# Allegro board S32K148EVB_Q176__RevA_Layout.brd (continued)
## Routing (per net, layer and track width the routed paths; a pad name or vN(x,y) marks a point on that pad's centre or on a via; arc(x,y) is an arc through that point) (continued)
PTE10/CLKOUT/LPSPI2_PCS1/FTM2_C: length 203.9
  TOP w0.16: U7.6 v1(74.79,63.24) ; U8.11 v1(74.3,68.04)
  TOP w0.406: R219.1 v1(100.42,41.74) ; v1(33.72,12.15) 33.62,12.05 33.39,12.05 R310.1
  L3_INT_1 w0.191: v1(33.72,12.15) 33.72,14.58 24.89,23.42 24.89,42.47 25.25,42.84 25.25,45.71 24.95,46.01 24.95,47.7 26.09,48.84 26.09,55.95 25.25,56.78 25.25,59.29 26.22,60.25 26.22,60.9 26.24,60.93 26.24,60.96 26.25,60.96 26.25,61.36 26.22,61.38 26.22,68.27 18.6,75.89 18.29,75.89 17.34,76.84 17.34,82.65 18.3,83.61 21.75,83.61 22.73,82.63 22.73,79.53 23.38,78.87 25.28,78.87 J2.20 ; v1(84.54,59.04) 91.76,51.82 91.76,42.86 93.35,41.27 99.94,41.27 v1(100.42,41.74)
  L6_INT_2 w0.191: v1(84.54,59.04) 85.31,59.81 85.31,62.67 83.93,64.04 ; J2.20 27.81,78.54 27.81,76.99 30.23,74.56 38.67,74.56 38.78,74.45 43.83,74.45 51.01,67.26 52.24,67.26 52.74,66.76
  L6_INT_2 w0.203: 52.74,66.76 55.79,66.76 56.17,66.38 73.28,66.38 74.3,67.39 v1(74.3,68.04) ; 83.93,64.04 83.38,64.6 82.44,64.6 81.55,65.49 78.98,65.49 77.33,63.84 75.5,63.84 74.9,63.24 v1(74.79,63.24)
  BOTTOM w0.16: v1(74.3,68.04) 74.3,66.75 74.79,66.26 v1(74.79,63.24)
PTE11/FTM2_CH5/FXIO_D5: length 158.4
  TOP w0.16: U7.5 v1(75.29,62.77) ; U8.10 v1(74.8,67.57)
  TOP w0.406: R309.1 31.43,11.87 31.43,12.21 31.48,12.25 v1(31.48,12.22)
  L3_INT_1 w0.191: v1(31.48,12.22) 31.48,16.37 24.57,23.29 24.57,42.6 24.93,42.97 24.93,45.58 24.63,45.88 24.63,47.84 25.77,48.98 25.77,55.79 24.94,56.63 24.94,61.21 25.74,62.01 25.74,62.02 25.76,62.04 25.76,62.44 25.74,62.46 25.74,68.31 18.47,75.58 18.16,75.58 17.02,76.71 17.02,82.78 18.17,83.93 23.98,83.93 24.94,82.96 24.94,81.07 J2.23
  L6_INT_2 w0.191: J2.23 24.95,78.86 24.95,77.3 28.02,74.24 38.55,74.24 38.65,74.13 43.69,74.13 50.88,66.95 51.98,66.95 52.52,66.41 52.74,66.41
  L6_INT_2 w0.203: 52.74,66.41 55.64,66.41 56.03,66.03 73.73,66.03 74.8,67.09 v1(74.8,67.57)
  BOTTOM w0.16: v1(75.29,62.77) 75.29,67.08 v1(74.8,67.57)
PTE12/FTM0_FLT3/LPUART2_TX/FTM5: length 37.4
  TOP w0.16: U8.30 v1(64.79,67.57) ; U7.23 v1(66.29,62.77)
  L3_INT_1 w0.191: J6.20 74.73,78.54 74.73,76.97 74.08,76.32 73.16,76.32 72.19,77.29 72.19,80.43 71.54,81.08 68.08,81.08 65.7,78.7 65.7,73.21 64.79,72.3 64.79,69.05
  L3_INT_1 w0.203: 64.79,69.05 v1(64.79,67.57)
  BOTTOM w0.16: v1(64.79,67.57) 64.79,66.23 66.29,64.72 v1(66.29,62.77)
PTE13/FTM4_CH5/LPSPI2_PCS2/FTM2: length 95.7
  TOP w0.16: U7.7 v1(74.29,62.77) ; U8.12 v1(73.8,67.57)
  TOP w0.406: J6.23 74.84,78.75 74.84,76.86 v1(75.95,75.75) ; R220.1 v1(101.43,41.74)
  L3_INT_1 w0.191: J6.23 74.97,81.32 74.97,82.87 75.95,83.86 91.61,83.86 94.04,81.42 94.04,76.54 98.76,71.82 98.76,60.66 96.72,58.61 96.72,56.56 96.24,56.08 96.24,55.47 93.52,52.75 93.52,47.65 94.32,46.84 94.55,46.84 98.83,42.56 101.1,42.56 101.43,42.22 v1(101.43,41.74)
  BOTTOM w0.16: v1(74.29,62.77) 74.29,66.28 73.8,66.78 v1(73.8,67.57)
  BOTTOM w0.203: 73.8,69.05 v1(73.8,67.57)
  BOTTOM w0.406: v1(75.95,75.75) 76.36,75.34 76.36,71.61 73.8,69.05
PTE14/FTM0_FLT1/FTM2_FLT1: length 23.2
  TOP w0.16: U7.20 v1(67.79,63.24) ; U8.27 v1(66.29,68.04)
  BOTTOM w0.16: v1(67.79,63.24) 67.79,64.75 66.29,66.25 v1(66.29,68.04)
  BOTTOM w0.203: v1(66.29,68.04) 66.29,68.53 66.81,69.05
  BOTTOM w0.406: 66.81,69.05 66.81,71.13 72.3,76.62 72.3,78.75 J6.26
PTE15/LPSPI2_SCK/FTM2_CH6/FTM4_: length 152.9
  TOP w0.16: U8.5 v1(77.3,68.04) ; U7.2 v1(76.79,63.24)
  TOP w0.406: R312.1 37,11.39 v1(36.56,11.82) ; R36.2 18.68,74.89 v1(18.58,74.79)
  TOP w0.635: J2.28 19.52,76.67 R36.2
  L3_INT_1 w0.191: v1(18.58,74.79) 24.45,68.92 24.45,63.14 24.14,62.83 24.14,56.97 25.46,55.66 25.46,49.12 23.98,47.65 23.98,32.82 24.25,32.55 24.25,20.41 29.71,14.96 29.71,12.46 30.8,11.36 36.11,11.36 v1(36.56,11.82)
  L6_INT_2 w0.191: v1(18.58,74.79) 25.13,74.79 26,73.92 38.41,73.92 38.52,73.82 42.28,73.82 47.98,68.11 49.27,68.11 50.75,66.63 51.84,66.63 52.22,66.26 52.22,66.26 52.42,66.05 52.74,66.05
  L6_INT_2 w0.203: 52.74,66.05 55.5,66.05 55.88,65.67 75.58,65.67 77.3,67.39 v1(77.3,68.04)
  BOTTOM w0.16: v1(76.79,63.24) 77.3,63.74 v1(77.3,68.04)
PTE16/LPSPI2_SIN/FTM2_CH7/FTM4_: length 141.5
  TOP w0.16: U8.4 v1(77.8,67.57)
  TOP w0.203: v1(77.99,63.49) 77.8,63.3 77.52,63.3 77.29,63.52 U7.1
  TOP w0.406: R311.1 v1(35.27,12.14) ; v1(22.57,73.62) R37.2 22.57,76.16 J2.25
  L3_INT_1 w0.191: v1(35.27,12.14) 35.27,13.65 26.14,22.78 26.14,31.65 25.71,32.08 25.71,45.7 25.27,46.14 25.27,46.61 25.55,46.89 25.62,46.89 26.41,47.68 26.41,57.05 25.57,57.89 25.57,58.94 27.29,60.66 27.29,60.97 27.3,60.98 27.3,61.37 27.29,61.38 27.29,68.9 v1(22.57,73.62)
  L6_INT_2 w0.191: 52.74,65.69 52.33,65.69 51.9,66.12 51.71,66.31 50.62,66.31 49.14,67.79 47.85,67.79 42.14,73.5 38.38,73.5 38.28,73.6 29.86,73.6 29.54,73.28 22.9,73.28 v1(22.57,73.62)
  L6_INT_2 w0.203: 52.74,65.69 55.26,65.69 55.64,65.31 76.02,65.31 77.8,67.09 v1(77.8,67.57)
  BOTTOM w0.203: v1(77.99,63.49) 77.99,66.9 77.8,67.09 v1(77.8,67.57)
PTE17/FTM7_CH5/FXIO_D5: length 58.5
  TOP w0.203: v1(83.3,48.96) 82.72,48.96 82.69,48.93 82.67,48.93 82.67,48.93 U8.145
  BOTTOM w0.203: v1(83.3,48.96) 83.99,49.64 83.99,50.76 84.85,51.62 84.85,53.33 86.09,54.57 86.1,54.57 88.51,56.98 88.51,57.25 88.51,57.8 88.51,67.11 88.76,67.37 88.76,67.64 88.76,67.64 88.76,68.19 88.76,73.24 87.27,74.74 86.99,74.74 86.64,74.74 86.54,74.84 84.79,74.84 82.56,77.07 82.56,82.77 81.37,83.96 76.03,83.96 74.94,82.87 74.94,82.25 74.08,81.39 69.66,81.39 J6.30
PTE18/FTM7_CH6/FXIO_D4: length 50.8
  TOP w0.203: v1(83.4,49.95) 82.73,49.95 82.71,49.93 U8.147
  TOP w0.406: v1(81.85,74.86) 79.56,74.86 77.5,76.93 77.5,80.52 76.71,81.3 72.29,81.3 J6.27
  BOTTOM w0.203: v1(81.85,74.86) 82.31,74.41 86.58,74.41 86.86,74.41 87.13,74.41 88.43,73.11 88.43,68.05 88.43,67.78 88.43,67.5 88.18,67.25 88.18,57.66 88.18,57.66 88.18,57.39 88.18,57.12 85.96,54.9 85.95,54.9 84.42,53.37 84.42,51.8 83.4,50.79 v1(83.4,49.95)
PTE19/FTM7_CH7/FTM7_CH7/ADC1__1: length 115.3
  TOP w0.203: v1(77.89,53.2) 78.16,52.93 U7.125 80.25,52.93 80.25,52.93 U8.153
  L3_INT_1 w0.191: v1(53.47,42.67) 51.31,40.52 51.31,38.18 53.43,36.06 53.43,32.56 v1(54.7,31.28)
  L6_INT_2 w0.191: J4.19 64.88,30.29 61.88,30.29 61.49,30.68 60.88,30.68 60.33,31.23 55.23,31.23 55.18,31.28 v1(54.7,31.28) 51.47,31.28 51.22,31.04 36.44,31.04 33.31,34.17 32.35,34.17 29.46,37.07 29.46,42.84 35.4,48.78 35.4,49.45 36.94,50.99 36.94,53.24 34.84,55.34 33.19,55.34 32.63,55.9 31.31,55.9 30.55,56.66 30.55,56.69 v1(29.99,57.25)
  L6_INT_2 w0.203: v1(75.81,50.4) 77.89,52.49 v1(77.89,53.2)
  BOTTOM w0.203: v1(53.47,42.67) 53.7,42.44 57.28,42.44 60.29,45.45 62.23,45.45 62.48,45.71 65.21,45.71 69.91,50.4 v1(75.81,50.4)
  BOTTOM w0.406: v1(29.99,57.25) 29.99,57.25 29.99,57.25 29.98,57.25 30.44,57.71 R528.1
PTE19/FTM7_CH7/FTM7_CH7/ADC1_SE: length 8.4
  TOP w0.279: R139.2 26.97,58.09 26.11,58.09 v1(26.05,58.15)
  L3_INT_1 w0.191: v1(26.05,58.15) 26.23,58.15 29.1,61.03 v1(29.1,62.15)
  BOTTOM w0.203: U501.7 TP502.1
  BOTTOM w0.406: v1(29.1,62.15) 29.1,62.15 29.1,62.14 28.79,61.83 TP502.1
PTE20/FTM4_CH0/FTM4_CH0/ADC1__1: length 141.8
  TOP w0.203: v1(77.28,53.68) 78.14,53.68 78.39,53.43 U7.126 80.25,53.43 80.25,53.43 U8.154
  L3_INT_1 w0.191: v1(40.27,48.91) 40.27,49.77 46.85,56.35 v1(52.77,56.35) ; v1(30.29,31.96) 30.29,43.19 27.6,45.88 27.6,54.52 28.5,55.42 28.5,55.93 v1(28.16,56.27)
  L6_INT_2 w0.191: v1(77.28,53.68) 76.8,54.16 63.25,54.16 59.5,50.41 58.79,50.41 57.83,49.45 54.33,49.45 53.97,49.09 53.54,49.09 52.77,49.86 v1(52.77,56.35) ; v1(49.87,30.51) 51.63,30.51 51.87,30.27 61.38,30.27 62.14,29.5 62.14,28.94 63.01,28.07 67.44,28.07 J4.22 ; v1(40.27,48.91) 40.27,49.38 39.94,49.72 39.94,52.59 37.27,55.26 37.27,55.92 35.88,57.31 32.04,57.31 30.38,58.97 29.71,58.97 28.16,57.42 v1(28.16,56.27)
  BOTTOM w0.406: v1(28.16,56.27) 28.16,56.27 28.16,56.25 28.59,55.81 R534.1 ; v1(49.87,30.51) 49.29,30.51 49.13,30.67 31.58,30.67 v1(30.29,31.96)
PTE20/FTM4_CH0/FTM4_CH0/ADC1_SE: length 3.4
  TOP w0.203: R124.2 26.68,61 26.81,61.12 26.81,61.17 v1(26.82,61.17)
  BOTTOM w0.203: v1(26.82,61.17) 26.81,61.17 26.81,61.3 26.99,61.48 TP501.1 27.9,61.15 28.13,61.15 28.39,60.89 U501.6
PTE21: length 6.2
  TOP w0.203: v1(76.95,54.7) 77.43,54.7 77.7,54.43 U7.128 80.25,54.43 80.25,54.43 U8.156
  BOTTOM w0.203: R544.1 R541.1 v1(76.95,54.7)
PTE21/FTM4_CH1/FTM4_CH1/ADC1_SE: length 34.7
  L3_INT_1 w0.191: J5.1 78.15,33.7 79.71,33.7 80.24,34.22 80.24,36.57 82.28,38.62
  L3_INT_1 w0.203: 82.28,38.62 82.28,40.24 80.2,42.32 80.2,49.02 78.02,51.19 77.64,51.19 v1(74.13,54.7)
  BOTTOM w0.203: v1(74.13,54.7) R541.2
PTE22: length 6.4
  TOP w0.203: v1(76.95,55.71) 77.43,55.71 78.21,54.93 U7.129 80.25,54.93 80.25,54.93 U8.157
  BOTTOM w0.203: v1(76.95,55.71) R538.1 R533.1
PTE22/FTM4_CH2/FTM4_CH2/ADC1_SE: length 36.2
  L3_INT_1 w0.191: J5.3 79.5,32.5 79.5,33.03 81.01,34.55 81.01,36.74 82.64,38.37 82.64,38.62
  L3_INT_1 w0.203: v1(74.16,55.71) 74.64,56.2 77.15,56.2 77.62,55.73 77.62,55.12 80.56,52.18 80.56,42.47 82.64,40.39 82.64,38.62
  BOTTOM w0.203: v1(74.16,55.71) R538.2
PTE23: length 7.1
  TOP w0.203: v1(78.1,55.93) U7.131 80.25,55.93 80.25,55.93 U8.159
  BOTTOM w0.203: v1(78.1,55.93) 78.1,56.41 76.77,57.74 R529.1 R524.1
PTE23/FTM4_CH3/FTM4_CH3/ADC1_SE: length 36.9
  L3_INT_1 w0.191: 82.99,38.62 82.99,38.24 81.33,36.57 81.33,34.42 79.81,32.9 79.81,32.24 78.7,31.13 J5.5
  L3_INT_1 w0.203: v1(74.23,58.76) 75.95,58.76 78.79,55.92 78.79,54.45 80.91,52.33 80.91,42.62 82.99,40.53 82.99,38.62
  BOTTOM w0.203: v1(74.23,58.76) R524.2
PTE24/FTM4_CH4/CAN2_TX/FTM4_CH4: length 36.4
  TOP w0.16: U8.160 v1(82.44,56.43)
  TOP w0.203: U8.160 80.25,56.43 80.25,56.43 U7.132
  L3_INT_1 w0.191: J5.7 82.34,30.27 83.09,30.27 87.38,34.56 87.38,43.82 87.38,43.83 87.38,52.98 85.74,54.62 85.09,54.62 83.93,55.77
  L3_INT_1 w0.203: v1(82.44,56.43) 83.27,56.43 83.93,55.77
PTE25/FTM4_CH5/CAN2_RX/CAN2_RX/: length 36.1
  TOP w0.16: U8.161 v1(82.91,56.93)
  TOP w0.203: U8.161 80.25,56.93 80.25,56.93 U7.133
  L3_INT_1 w0.191: J5.9 84.86,30.24 84.87,30.24 88.02,33.39 88.02,44.08 88.01,44.09 88.01,53.25 84.89,56.37 83.93,56.37
  L3_INT_1 w0.203: v1(82.91,56.93) 83.28,56.93 83.84,56.37 83.93,56.37
PTE26/FTM4_CH6: length 29.3
  TOP w0.16: U8.167 v1(82.9,59.94)
  BOTTOM w0.203: v1(82.9,59.94) 83.69,60.72 83.93,60.72
  BOTTOM w0.406: J6.18 79.91,81.3 79.91,76.41 79.62,76.12 79.62,74.76 85.92,68.46 85.92,61.91 84.72,60.72 83.93,60.72
PTE27/FTM4_CH7: length 25.2
  TOP w0.16: U8.174 v1(82.44,63.44)
  BOTTOM w0.203: 83.93,64.11 83.27,63.44 v1(82.44,63.44)
  BOTTOM w0.406: J6.21 77.43,81.24 77.43,75.73 84.67,68.49 84.67,64.84 83.93,64.11
PVEXT_SBC: length 30.2
  TOP w0.33: U9.2 27.37,48.85 27.55,48.68 27.55,47.99 27.98,47.56
  TOP w0.508: R204.2 29.03,46.43 v1(28.43,46.43) 27.99,46.88 27.99,47.11 27.98,47.11 27.98,47.56
  TOP w0.635: TPAD39.1 C60.1 ; C60.1 TS11.1 v1(30.16,46.24) 29.81,46.59 R204.2 ; C60.1 32.02,44.08 C57.1 C54.1
  L5_PWR_2 w0.635: v1(19.95,55.94) 20.21,55.94 v1(20.56,56.3) 20.56,60.23 20.15,60.64 v1(20.15,65.82)
  BOTTOM w0.406: v1(20.56,56.3) 20.56,56.88 20.8,57.12 20.8,58.58 20.42,58.95 R527.1
  BOTTOM w0.635: R632.2 v1(20.15,65.82)
SAI0_BCLK: length 2.3
  TOP w0.406: P1.11 R325.2
SAI0_DATA0: length 2.3
  TOP w0.406: P1.9 R326.2
SAI0_DATA1: length 2.3
  TOP w0.406: P1.7 R327.2
SAI0_DATA2: length 2.3
  TOP w0.406: P1.5 R328.2
SAI0_DATA3: length 2.3
  TOP w0.406: P1.3 R329.2
SAI0_MCLK: length 2.3
  TOP w0.406: P1.15 R323.2
SAI0_SYNC: length 2.3
  TOP w0.406: P1.13 R324.2
SBC_CANH: length 4.8
  TOP w0.254: R112.1 17.95,60.69 18.68,59.95
  TOP w0.279: U9.21 19.04,58.57 18.92,58.69 18.92,59.72 18.68,59.95
  TOP w0.406: R119.1 R112.1
SBC_CANL: length 5.4
  TOP w0.254: R134.1 18.26,59.8 18.39,59.67
  TOP w0.279: R135.1 16.29,59.07 ; U9.22 18.39,58.57 18.51,58.69 18.51,59.55 18.39,59.67
  TOP w0.406: 16.29,59.07 R134.1
SBC_EN: length 26.6
  TOP w0.279: U9.5 25.19,50.8 24.84,50.45 v1(24.32,50.45)
  L3_INT_1 w0.191: v1(24.32,50.45) 24.83,49.94 24.87,49.94 25.14,49.68 25.14,49.26 23.33,47.46 23.33,36.64 v1(20.99,34.3)
  L6_INT_2 w0.191: v1(20.99,34.3) 18.4,34.3 J15.7
SBC_HVIO1: length 55.6
  TOP w0.279: 16.57,44.77 16.8,44.99 16.83,44.99 17.09,45.25 U9.37
  TOP w0.406: v1(15.56,44.54) TP30.1 16.57,44.77 ; R4.1 v1(5.75,78.86)
  L3_INT_1 w0.191: v1(5.75,78.86) 6.49,78.86 12.4,72.96 12.4,47.69 v1(15.56,44.54)
  L6_INT_2 w0.191: J14.1 15.56,32.73 15.56,33.65 15.35,33.86 15.35,34.26 15.56,34.47 v1(15.56,44.54)
SBC_HVIO2: length 21.6
  TOP w0.279: 13.25,46.7 v1(14.26,46.7) ; U9.36 13.46,48.2 13.25,47.99
  TOP w0.406: 13.25,47.99 R203.2 TP28.1 13.25,46.7
  L3_INT_1 w0.191: J14.3 13.35,39.51 16.35,42.51 16.35,44.61 v1(14.26,46.7)
SBC_HVIO3: length 20.8
  TOP w0.279: v1(13.35,48.85) U9.35
  L6_INT_2 w0.191: J14.4 12.27,31.59 12.27,47.78 v1(13.35,48.85)
SBC_HVIO4: length 24.4
  TOP w0.279: U9.34 v1(13.78,49.5)
  L6_INT_2 w0.191: v1(13.78,49.5) 13.32,49.5 12.87,49.05 12.87,48.89 11.96,47.97 11.96,30.75 13.01,29.7 13.8,29.7 J14.2
SBC_HVIO5: length 32
  TOP w0.279: U9.33 15.98,50.15 16.47,49.66 v1(16.47,48.85)
  L6_INT_2 w0.191: J15.8 14.75,29.38 12.88,29.38 11.45,30.81 11.45,48.87 12.55,49.98 13.98,49.98 15.1,48.85 v1(16.47,48.85)
SBC_HVIO6: length 30.9
  TOP w0.279: v1(13.78,50.8) U9.32
  L6_INT_2 w0.191: v1(13.78,50.8) 12.93,50.8 10.28,48.15 10.28,31.53 12.75,29.06 14.98,29.06 15.5,29.58 16.22,29.58 J15.6
SBC_HVIO7: length 27.7
  TOP w0.279: U9.31 v1(17.13,51.45)
  L3_INT_1 w0.191: v1(17.13,51.45) 19.77,48.8 19.77,34.73 20.83,33.67 20.83,30.49 20.04,29.7 19.25,29.7 J15.4
SBC_HVIO8: length 25.1
  TOP w0.279: U9.30 v1(16.44,52.1)
  L3_INT_1 w0.191: J15.2 20.52,31.33 20.52,33.3 19.44,34.38 19.44,48.46 16.44,51.46 v1(16.44,52.1)
SBC_LIMP: length 20.4
  TOP w0.279: U9.39 v1(18.39,47.4)
  TOP w0.406: D7.C v1(14.62,39.48)
  L3_INT_1 w0.191: v1(18.39,47.4) 18.39,43.25 v1(14.62,39.48) 14.62,34.33 J15.5
SBC_LIN_OUT1: length 3.7
  TOP w0.279: v1(16.83,55.76) 16.83,55.84 17.09,56.1 U9.24
  BOTTOM w0.406: R543.1 R542.1 16.83,55.53 v1(16.83,55.76)
SBC_LIN_OUT2: length 3.4
  TOP w0.279: v1(13.73,55.57) 13.95,55.35 U9.25
  BOTTOM w0.406: v1(13.73,55.57) 13.54,55.57 R535.1 R530.1
SBC_OE: length 64.3
  L3_INT_1 w0.203: v1(24.66,49.48) 24.18,49.48 23.84,49.82 23.84,50.99 24.14,51.29 24.14,53.6 18.89,58.86 v1(17.58,58.86) ; v1(31.03,52.34) 31.03,52.82 31.03,52.83 31.03,54.42 32.32,55.71 v1(32.32,56.83) ; v1(28.41,64.55) 28.41,61.01 28.15,60.75 28.03,60.75 v1(27.69,60.41)
  L6_INT_2 w0.191: v1(31.03,52.34) 30.49,51.79 27.13,51.79 24.8,49.46 24.68,49.46 24.68,49.48 24.66,49.48 24.66,49.48 v1(24.66,49.48)
  L6_INT_2 w0.203: v1(27.69,60.41) 26.14,58.86 v1(17.58,58.86) ; v1(28.41,64.55) 25.31,64.55 v1(21.98,61.22)
  BOTTOM w0.203: U504.5 22.14,57.74 R525.1 22.61,58.37 22.61,60.12 21.98,60.74 v1(21.98,61.22) ; v1(27.69,60.41) 28.04,60.06 U501.5 ; v1(32.32,56.83) 32.32,57.43 32.66,57.77 U503.5 ; v1(28.41,64.55) 27.83,63.97 U500.5 ; v1(17.58,58.86) 17.44,58.86 17.16,58.86 U502.5 ; U507.5 25.16,49.46 25.14,49.48 v1(24.66,49.48) ; v1(31.03,52.34) 31.51,52.34 31.52,52.33 31.84,52.33 32.04,52.13 U506.5
SBC_RESET: length 12.3
  L6_INT_2 w0.191: v1(25.76,56.95) 26.57,56.95 29.23,59.61 31.81,59.61 v1(32.25,59.17)
  BOTTOM w0.203: U503.7 34,59.12 33.82,59.29 32.85,59.29 32.73,59.17 v1(32.25,59.17)
  BOTTOM w0.406: v1(25.76,56.95) 25.77,56.95 25.77,56.96 26.2,57.39 26.26,57.39 26.32,57.44 R532.1 ; TP503.1 31.79,59.62 v1(32.25,59.17)
SDA_EXTAL: length 7.7
  BOTTOM w0.279: U510.17 20.15,18.65 20.59,19.09 20.59,20.03 20.82,20.25 20.82,21.86 21.25,22.29 Y501.3 23.82,22.29 C534.1
SDA_JTAG_TCLK: length 14.9
  L3_INT_1 w0.191: J20.4 20.33,23.17 v1(17.26,20.09)
  L6_INT_2 w0.191: J20.4 20.33,23.85 20.45,23.73 24.83,23.73 24.89,23.78 v1(25.36,23.78)
  BOTTOM w0.279: v1(17.26,20.09) 17.24,20.09 U510.12
  BOTTOM w0.508: R608.1 v1(25.36,23.78)
SDA_JTAG_TDI: length 10.1
  TOP w0.203: J20.8 17.79,23.73 17.54,23.48
  TOP w0.406: 17.54,23.48 16.07,23.48 R281.2
  BOTTOM w0.203: J20.8 17.79,23.91 17.74,23.86 U510.13
SDA_JTAG_TDO: length 21.4
  L6_INT_2 w0.191: v1(19.96,28.61) 19.57,28.22 16,28.22 15.15,27.37 15.15,24.14 15.79,23.51 18.78,23.51 19.06,23.78 J20.6
  BOTTOM w0.203: U510.14 18.24,22.83 19.06,23.66 J20.6
  BOTTOM w0.406: R605.2 v1(19.96,28.61)
SDA_JTAG_TMS: length 10
  BOTTOM w0.203: U510.15 18.74,21.45 19.81,22.53 19.99,22.53 21.6,24.14 J20.2
  BOTTOM w0.635: J20.2 21.91,24.98 23.71,24.98 R606.2
SDA_LED: length 2.6
  TOP w0.406: D10.C 17.3,13.01 16.95,13.36 v1(16.95,13.4)
  BOTTOM w0.279: U510.29 17.24,13.68 16.96,13.4 v1(16.95,13.4)
SDA_LED_R: length 3.7
  TOP w0.406: R308.2 15.2,10.93 15.75,11.48 D10.A
SDA_RST: length 21.2
  L3_INT_1 w0.191: J20.10 16.52,24.67 15.66,23.81 15.66,20.2 16.75,19.11 22.19,19.11 v1(22.62,18.68)
  BOTTOM w0.279: v1(22.62,18.68) R612.1 R615.2 ; U510.19 20.53,17.65 20.55,17.67 20.87,17.67 21.12,17.92 TP510.1
  BOTTOM w0.406: R615.2 23.2,17.92 TP510.1 ; R607.2 15.33,25.31 15.66,24.98 16.22,24.98 J20.10
SDA_RST_LED: length 1.1
  TOP w0.406: R337.1 9.42,2.87 D11.A
SDA_RST_TGTMCU_B: length 36.3
  BOTTOM w0.279: J23.2 51.09,13.94 48.11,10.96 38.32,10.96 33.52,15.76 32.02,15.76 31.94,15.83 27.29,15.83 26.05,17.08 23.13,17.08 23.03,17.18 21.55,17.18 20.99,16.62 20.56,16.62 20.53,16.65 U510.21
SDA_RST_TGTMCU_J_B: length 25.5
  TOP w0.406: R295.1 v1(46.6,15.76)
  L3_INT_1 w0.191: J23.1 48.35,17.51 v1(46.6,15.76) 45.63,15.76 J22.3
  L6_INT_2 w0.191: v1(46.6,15.76) 45.05,17.31 34.28,17.31 v1(33.69,17.89)
  BOTTOM w0.203: U509.2 33.9,18.15 33.69,17.95 v1(33.69,17.89) 33.59,17.89 R616.2
SDA_RX_EN: length 2.1
  BOTTOM w0.305: R630.1 R631.2 17.89,10.27 U514.5
SDA_SPI0_CS: length 21.1
  TOP w0.406: v1(12.15,21.68) 12.87,20.97 14.69,20.97 17.08,18.58 R290.2
  L3_INT_1 w0.191: v1(21.55,15) 18.58,17.97 16.6,17.97 13.75,20.81 13.02,20.81 v1(12.15,21.68)
  BOTTOM w0.279: U510.23 20.9,15.65 v1(21.55,15)
SDA_SPI0_RST_B: length 4
  TOP w0.406: v1(21.55,16.44) R292.2 TP57.1
  BOTTOM w0.279: v1(21.55,16.44) 21.55,16.43 21.27,16.15 U510.22
SDA_SPI0_SCK: length 17.3
  L6_INT_2 w0.191: v1(19.14,13.56) 19.66,13.04 22.77,13.04 23.75,12.06 28.44,12.06 29.76,13.38 31.52,13.38 v1(32.85,14.72)
  BOTTOM w0.279: v1(32.85,14.72) 32.75,14.61 U511.3 ; U510.26 18.74,14 19.14,13.6 19.14,13.55 19.14,13.55 v1(19.14,13.56)
SDA_SPI0_SIN: length 5.7
  L6_INT_2 w0.191: v1(21.2,12.46) 18.68,12.46 v1(17.79,13.35)
  BOTTOM w0.279: v1(21.2,12.46) 21.25,12.46 21.51,12.72 U513.5 ; v1(17.79,13.35) 17.79,13.4 17.74,13.45 U510.28
SDA_SPI0_SOUT: length 12.6
  L6_INT_2 w0.279: v1(28.21,14.92) 27.76,14.48 25.32,14.48 24.54,13.69 20.12,13.69 19.72,14.08 18.93,14.08 18.46,13.61 v1(18.46,13.51)
  BOTTOM w0.279: v1(18.46,13.51) 18.24,13.73 U510.27 ; U512.3 27.9,14.49 28.18,14.77 28.18,14.89 v1(28.21,14.92)
SDA_SWD_EN: length 18.2
  TOP w0.305: v1(29.32,12.13) 30.01,12.81 30.01,17.49 27.77,19.72 22.75,19.72 R292.1
  TOP w0.406: R292.1 20.75,19.33 U23.6
  BOTTOM w0.406: R624.1 29.81,12.61 v1(29.32,12.13)
SDA_SWD_EN_B: length 2.3
  BOTTOM w0.279: R609.2 19.95,20.74 19.95,19.58 19.67,19.3 U510.16
SDA_SWD_EN_B_R: length 6.5
  TOP w0.406: v1(22.59,23.16) 22.87,22.88 R286.2 22.23,21.98 21.69,22.52 U23.1
  BOTTOM w0.279: R609.1 21.36,23.16 v1(22.59,23.16)
SDA_SWD_EN_R: length 4
  BOTTOM w0.229: R622.2 30.82,12.71 R623.1 31.71,13.09 U511.5
SDA_SWD_OE: length 15.7
  TOP w0.305: v1(28.66,13.33) 27.33,14.67 24.83,14.67 23.96,15.53 19.55,15.53 18.77,16.3 18.77,18.49 R290.1 18.86,19.23 18.85,19.24 U23.4
  BOTTOM w0.406: R625.1 v1(28.66,13.33)
SDA_SWD_OE_B: length 13.9
  TOP w0.406: R284.2 15.9,21.5 15.65,21.75 v1(13.14,21.75)
  L3_INT_1 w0.191: v1(13.14,21.75) 13.63,21.75 16.7,18.68 19.24,18.68 v1(20.76,17.15)
  BOTTOM w0.279: U510.20 v1(20.76,17.15)
SDA_SWD_OE_B_R: length 2.3
  TOP w0.406: U23.3 17.54,22.52 R285.1 R284.1
SDA_SWD_OE_R: length 7.7
  L3_INT_1 w0.191: v1(27.17,11.31) 27.17,12.81 v1(26.02,13.96)
  BOTTOM w0.279: R626.1 27.22,12.15 R625.2 27.14,13.09 U512.5
  BOTTOM w0.406: R621.2 25.36,14.62 v1(26.02,13.96) ; v1(27.17,11.31) 26.78,11.69 R626.1
SDA_USB_CONN_DN: length 5.5
  TOP w0.229: v1(5.83,12.41) 5.59,12.65 5.26,12.65 5.13,12.52 J24.2
  BOTTOM w0.229: v1(5.83,12.41) 6.12,12.69 6.44,12.69 6.67,12.46 6.67,11.87 7.15,11.39 7.66,11.39 7.98,11.07 U515.4
SDA_USB_CONN_DP: length 5.5
  TOP w0.229: J24.3 5.13,13.17 5.29,13.01 5.51,13.01 v1(5.83,13.33)
  BOTTOM w0.229: U515.6 7.98,12.07 7.66,11.75 7.3,11.75 7.02,12.02 7.02,12.61 6.59,13.05 6.12,13.05 v1(5.83,13.33)
SDA_USB_DN: length 2.3
  BOTTOM w0.229: U510.4 14.4,16.65 14.26,16.51 13.92,16.51 13.73,16.32 13.37,16.32 R617.2
SDA_USB_DP: length 2.3
  BOTTOM w0.229: U510.3 14.07,16.15 13.88,15.96 13.37,15.96 R618.2
SDA_USB_P5V_SENSE: length 4.1
  BOTTOM w0.279: U510.30 16.74,13.97 15.51,12.74 R628.2 R629.1
SDA_USBSHIELD: length 13
  TOP w0.635: J24.10 J24.8 J24.9
  BOTTOM w0.279: J24.6 5.41,15.39 5.7,15.68 5.7,16.65 4.6,17.75 L501.1
SDA_VOUT33: length 6.1
  TOP w0.508: R291.2 11.87,18.86 v1(13.35,18.86)
  BOTTOM w0.279: U510.5 13.55,17.15 12.92,17.79 C541.1
  BOTTOM w0.406: C541.1 12.92,18.46 13.32,18.86 v1(13.35,18.86)
SDA_XTAL: length 5.6
  BOTTOM w0.279: U510.18 20.49,18.15 21.33,18.99 21.33,19.5 21.72,19.89 Y501.1 24.4,19.89 C537.1
SPLIT: length 4
  TOP w0.406: R125.2 11.09,61.43 11.65,60.87 C15.1 R138.1
SW1_RST_B: length 47
  TOP w0.406: SW5.2 8.55,4.47 8.54,4.48 8.45,4.48 8.22,4.71 8.22,9.29 8.55,9.62 SW5.4 9.37,8.2 9.72,7.86 v1(12.36,7.86)
  L6_INT_2 w0.191: v1(38.6,12.25) 37.29,10.93 28.54,10.93 27.81,10.2 14.7,10.2 v1(12.36,7.86)
  BOTTOM w0.406: J22.2 C543.1 41.62,15.26 v1(38.6,12.25)
SWD_CLK_TGTMCU_BUF: length 2.5
  TOP w0.406: v1(33.06,13.85) 33.64,13.85 33.81,14.02 R298.1
  BOTTOM w0.305: U511.4 v1(33.06,13.85)
SWD_DIO_TGTMCU_BUF: length 10.1
  TOP w0.406: R294.1 28.93,14.6 v1(28.92,14.59)
  L6_INT_2 w0.191: v1(28.92,14.59) 26.7,12.37 24.95,12.37 24.73,12.6 v1(24.26,12.6)
  BOTTOM w0.279: U513.2 23.63,13.22 v1(24.26,12.6)
  BOTTOM w0.406: U512.4 28.18,13.73 28.5,14.05 28.5,14.18 v1(28.92,14.59)
TC_EXTAL_TP: length 1.9
  BOTTOM w0.279: U510.10 16.24,19.87 15.58,20.52 TP508.1
TC_SDA_USB_ID_TP: length 4
  TOP w0.279: J24.4 5.26,13.82 v1(5.75,14.31)
  BOTTOM w0.406: v1(5.75,14.31) 6.34,14.31 6.64,14.62 TP512.1
TC_XTAL_TP: length 2.3
  BOTTOM w0.279: TP509.1 15.25,20.03 15.25,20 15.74,19.52 U510.9
TOUCH_ADC0_A: length 4.2
  TOP w0.279: C108.1 R330.1
  TOP w0.406: R302.1 C108.1
  TOP w0.508: C108.1 TPAD52.1
TOUCH_ADC0_B: length 4.6
  TOP w0.406: R274.1 R278.1 101.84,31.81 C78.1 TPAD46.1
TOUCH_ADC1_A: length 4.2
  TOP w0.406: TPAD53.1 R304.1 R333.1 R330.2
TOUCH_ADC1_B: length 4.6
  TOP w0.406: R280.1 TPAD47.1 105.35,33.01 R275.1 R278.2
UART1_RX_TGTMCU_BUF: length 3.6
  TOP w0.305: v1(19.39,11.01) 19.39,11.54 19.34,11.59 R305.1
  BOTTOM w0.305: v1(19.39,11.01) 19.29,10.9 18.61,10.9 18.39,11.12 U514.4
  BOTTOM w0.406: R627.1 v1(19.39,11.01)
UART1_RX_TGTMCU_R: length 3.4
  BOTTOM w0.279: U514.3 18.39,12.72 18.69,13.02 19.39,13.02 19.67,13.29 19.67,13.85 19.24,14.29 U510.25
UART1_TX_TGTMCU_BUF: length 2.2
  BOTTOM w0.279: R620.1 22.95,14.41 23.04,14.32 U513.1
  BOTTOM w0.406: R619.1 R620.1
UART1_TX_TGTMCU_R: length 3.5
  BOTTOM w0.279: U510.24 20.38,15.15 20.54,15 20.54,13.8 21.12,13.22 U513.6
V_TGTMCU: length 56.8
  TOP w0.305: R299.1 v1(36.42,15.59)
  TOP w0.508: v1(12.1,2.91) 11.34,2.91 11.32,2.88 R337.2 ; v1(36.42,15.59) 35.97,15.14 35.97,13.55 35.21,12.79 32.35,12.79 31.26,13.88 v1(30.63,13.88) 30.63,12.26 29.71,11.34 28.69,11.34 27.18,12.85 v1(26.25,12.85) 25.09,12.85 23.46,14.49 v1(22.34,14.49)
  L3_INT_1 w0.508: v1(22.34,14.49) 22.34,13.73 21.86,13.24 20.43,13.24 19.27,12.08 18.58,12.08 v1(17.26,10.75) ; v1(38.67,18.91) 38.67,17.84 v1(36.42,15.59)
  L6_INT_2 w0.508: v1(12.1,2.91) 11.54,3.46 11.54,8.09 14.17,10.71 16.58,10.71 16.62,10.75 v1(17.26,10.75)
  BOTTOM w0.203: R614.1 36.43,18.15 U509.8 ; v1(22.34,14.49) 22.44,14.39 22.44,13.82
  BOTTOM w0.229: C544.1 C542.1 R614.1 ; R611.1 38.67,18.96 v1(38.67,18.91)
  BOTTOM w0.279: C546.1 26.11,12.85 v1(26.25,12.85) 26.25,12.96 26.64,13.35 U512.6
  BOTTOM w0.305: v1(30.63,13.88) 30.65,13.85 U511.6 ; v1(17.26,10.75) 17.25,10.75 17.39,10.89 U514.6
  BOTTOM w0.508: C544.1 37.35,16.52 v1(36.42,15.59)
VCAN_SBC: length 4.2
  TOP w0.279: U9.20 19.69,56.59 19.29,56.2 v1(19.3,56.2)
  BOTTOM w0.406: R526.2 19.8,57.38 R527.2 19.82,56.73 19.3,56.2 v1(19.3,56.2)
VREFH: length 56.8
  TOP w0.508: J2.22 25.34,75.93 26.42,75.93 26.89,75.46 C1.1 TPAD6.1 v1(29.2,74.76)
  L4_PWR_1 w0.635: v1(29.2,74.76) 30.01,75.58 36.41,75.58 37.88,74.1 44.56,74.1 46.44,75.98 56.96,75.98 58.71,74.23 62.73,74.23 63.23,74.74 68.52,74.74 v1(71.49,71.77)
  BOTTOM w0.508: v1(71.49,71.77) 70.12,71.77 69.23,70.88 R506.2
VREFH_MCU: length 23.9
  TOP w0.203: v1(69.3,68.23) 69.3,67.75 69.29,67.74 U8.21 ; U7.14 70.79,63.29 70.83,63.26 v1(70.83,63.24)
  TOP w0.762: TPAD9.1 75.4,74.05 v1(75.37,74.03)
  TOP w1.016: TS1.1 v1(75.37,74.03)
  L4_PWR_1 w0.762: v1(69.3,68.23) 69.3,69.15 70.29,70.14 71.74,70.14 73.77,72.17 73.77,72.43 v1(75.37,74.03)
  BOTTOM w0.203: v1(70.83,63.24) 70.27,63.8 70.27,65.69 69.28,66.68 69.28,67.1 69.28,67.73 69.3,67.75 v1(69.3,68.23)
  BOTTOM w0.381: R508.1 69.08,69.23 69.3,69 v1(69.3,68.23)
  BOTTOM w0.508: R506.1 R508.1
VSUP: length 359
  TOP w0.305: U9.38 17.74,47.06 17.52,47.27 16.72,47.27 16.24,46.8
  TOP w0.406: R3.1 v1(121.67,79.27)
  TOP w0.508: 30.7,62.7 C13.1 ; C13.1 31.2,63.21 ; C13.1 30.19,63.21 ; v1(15.15,6.97) 15.15,7.69 14.35,8.49 R334.1 ; 31.46,63.21 C14.1 ; C14.1 31.97,62.7 ; C14.1 32.47,63.21 ; D4.C 22,65.57
  TOP w0.635: R106.1 35.03,63.6 ; R106.1 34.34,64.2 ; R106.1 35.03,64.79 ; J12.1 15.1,45.96 15.41,45.96 16.24,46.8 ; R215.1 v1(26.35,42.96) ; v1(9.62,49.53) 10.52,49.53 10.97,49.98 R189.1 ; L2.1 v1(39.32,62.28) ; R262.1 v1(15.82,34.06) ; R13.1 v1(6.11,74.72)
  TOP w0.889: 22,63.08 D4.C 21.11,64.32 ; C11.1 27.55,64.67 ; C11.1 26.53,62.7 ; C11.1 25.51,64.67
  L3_INT_1 w0.635: J12.1 11.14,42 J21.1
  L4_PWR_1 w0.635: J21.1 11.14,22.39 11.11,22.36 11.11,19.97 8.8,17.66 8.8,14.16 7.33,12.69 7.33,9.54 10.39,6.48 14.66,6.48 v1(15.15,6.97) 15.89,6.97 17.03,5.83 17.92,5.83 21.78,9.69 27.52,9.69 28.79,10.96 83.05,10.96 86.86,7.15 105.27,7.15 106.79,8.67 106.79,42.91 107.53,43.65 107.53,45.48 108.8,46.75 115.23,46.75 117.94,49.46 117.94,66.69 123.89,72.63 123.89,77.05 v1(121.67,79.27) ; v1(22.31,65.95) 29.27,65.95 31.81,63.41 38.19,63.41 v1(39.32,62.28)
  L5_PWR_2 w0.635: v1(26.35,42.96) 26.35,45.65 29.71,49.01 32.93,49.01 36.41,52.49 36.54,52.49 37.88,53.83 37.88,54.73 37.45,55.15 37.45,56.42 39.32,58.29 v1(39.32,62.28)
  L5_PWR_2 w0.762: v1(9.62,49.53) 11.16,47.99 11.16,46.54 J12.1
  L6_INT_2 w0.635: v1(22.31,65.95) v1(21.58,65.95) 20.41,64.78 17.56,64.78 12.26,70.09 10.05,70.09 6.11,74.03 v1(6.11,74.72)
  BOTTOM w0.635: v1(15.82,34.06) 10.58,39.3 10.58,43.22 11.65,44.28 J12.1 14.61,43.09 17.39,43.09 19.24,44.94 25.23,44.94 26.35,43.83 v1(26.35,42.96)
VTRG_EN: length 4.2
  TOP w0.406: U24.3 8.91,14.17 R300.2 R296.1 8.72,16.27 R293.2
VTRG_FAULT_B: length 3.3
  TOP w0.279: U24.4 13.26,14.17 13.58,13.85 R301.2 14.81,13.85 15.11,14.15 15.11,14.16 v1(15.12,14.16)
  BOTTOM w0.279: v1(15.12,14.16) 15.11,14.16 15.46,14.5 U510.32
N12195: length 10.7
  TOP w0.406: R306.1 92.25,11.45 SW3.2 SW3.4 93.08,4.62 93.11,4.66 C114.1 R335.1 95.08,4.63 TP60.1
N12333: length 3.2
  TOP w0.406: TP42.1 89.7,42.12 89.74,42.09 Q1.3 R229.2
N12731: length 8.4
  TOP w0.406: R194.1 C49.1 TS9.1 R186.2
N14568: length 10.9
  TOP w0.406: C115.1 99.7,4.61 99.68,4.62 SW4.4 SW4.2 98.86,11.45 R307.1 ; C115.1 R336.1 ; C115.1 TP61.1
N16745305: length 1
  TOP w0.635: C12.2 C10.1
N16745986: length 13.6
  TOP w0.279: 21.1,44.77 21.1,44.83 20.99,44.95 U9.43 ; U9.26 13.98,54.7 13.83,54.85 v1(13.78,54.85)
  TOP w0.406: 21.1,44.77 21.1,44.48 21.17,44.42 v1(21.17,44.18) ; 32.68,59.83 C16.1 ; 34.65,58.81 34.65,58.9
  TOP w0.635: L2.2 38.42,64.12 ; L2.2 37.92,64.72 ; L2.2 37.92,63.52 ; 32.25,57.57 C21.1 30.75,57.57 C22.1 ; 36.63,64.79 R106.2 36.63,63.6
  TOP w0.889: 34.65,58.9 C16.1 ; C16.1 36.61,59.83 ; C16.1 34.65,60.84
  vias: v1(31.94,61.3) v1(31.99,60.51)
N16746162: length 4.5
  TOP w0.279: U9.28 13.75,53.4 13.6,53.55 13.25,53.55
  TOP w0.406: 13.25,53.55 TP24.1
  TOP w0.635: R163.2 TP24.1 C43.1
N16749267: length 5.5
  TOP w0.279: U9.40 19.04,45.22 18.86,45.04 18.58,45.04 18.3,44.77
  TOP w0.406: 18.3,44.77 TP34.1 17.28,43.75 C62.2 C64.2
N16749274: length 4.9
  TOP w0.279: U9.41 19.69,44.98 19.47,44.77
  TOP w0.406: 19.47,44.77 TP37.1 18.81,44.1 C62.1 C64.1
N16751208: length 4.6
  TOP w0.279: U9.42 20.34,44.77
  TOP w0.406: C65.2 C63.2 20.31,43.11 TP38.1 20.34,44.41 20.34,44.77
N16751220: length 12.8
  TOP w0.279: U9.44 21.64,45.16 22.01,44.79 22.01,44.77
  TOP w0.406: 22.01,44.77 TP39.1 22.01,43.29 C63.1 C65.1 21.73,39.99 20.89,39.15 18.23,39.15 17.43,38.35 L8.1
N16751253: length 7.4
  TOP w0.279: U9.48 24.24,44.77
  TOP w0.406: 24.24,44.77 24.24,44.62 TP40.1 25.42,43.44 25.42,42.91 26.12,42.2 C67.2 C69.2
N16751262: length 13.3
  TOP w0.279: 22.94,44.77 U9.46
  TOP w0.406: 22.94,44.77 22.94,43.87 22.65,43.58 22.65,41.66 23.05,41.26 C67.1 C69.1 TP47.1 L8.2
N16752852: length 2.4
  TOP w0.279: 13.25,54.49 13.69,54.05 U9.27
  TOP w0.406: C29.1 13.25,54.49
N16754051: length 17.1
  TOP w0.279: U9.47 23.59,44.77
  TOP w0.406: v1(24.46,43.3) 24.47,43.3 24.47,43.32 24.3,43.14 TP41.1 23.58,43.83 23.59,43.83 23.59,44.77
  TOP w0.635: R216.1 27.77,43.09 v1(28.05,42.81) 28.56,42.3 C70.1 C71.1
  BOTTOM w0.406: v1(24.46,43.3) 25.04,43.3 26.69,41.64 27.65,41.64 28.05,42.05 v1(28.05,42.81)
N16755093: length 7.3
  TOP w0.279: U9.11 25.31,54.7 25.08,54.93 25.08,55.84 25.46,56.22 26.25,56.22 R139.1 27.83,57.01
  TOP w0.406: TPAD30.1 28.64,57.54 28.64,57.44 28.21,57.01 R140.2 27.83,57.01
N16755100: length 3.8
  TOP w0.279: 25.49,59.07 25.23,58.81 TPAD29.1 24.65,58.48 24.24,58.07 U9.13
  TOP w0.406: R124.1 26.66,59.4 26.46,59.4 26.46,59.4 25.98,59.4 25.97,59.4 R132.2 25.74,59.32 25.49,59.07
N16755551: length 5.4
  TOP w0.406: J12.2 11.89,40.21 D8.A
N16755555: length 7.3
  TOP w0.406: D8.C 7.49,38.86 7.94,39.3 8.14,39.3 8.17,39.33 TP45.1 R225.2 R226.2
N16762105: length 4.6
  TOP w0.889: J11.3 6.07,53.3 6.12,53.25 R180.1
N16823835: length 4.3
  TOP w0.406: R95.2 93.98,65.36 93.98,65.36 93.8,65.36 v1(93.55,65.11) 91.53,65.11
  BOTTOM w0.279: R95.2 94.32,65.11 v1(93.55,65.11)
N16823837: length 4.1
  TOP w0.406: J10.8 v1(93.56,63.84) R107.2
  BOTTOM w0.279: v1(93.56,63.84) R107.2
N16823868: length 6.3
  TOP w0.406: 91.53,67.65 93.08,67.65 93.36,67.93 v1(93.36,69.66) 93.61,69.91 93.78,69.91 93.8,69.94 R72.2
  BOTTOM w0.279: v1(93.36,69.66) 94.3,69.66 R72.2
N16823904: length 4.1
  TOP w0.406: R110.1 v1(93.69,62.57) 91.53,62.57
  BOTTOM w0.635: v1(93.69,62.57) R518.2
N16823906: length 7
  TOP w0.406: J10.4 93.27,66.38 93.47,66.58 93.5,66.58 v1(93.5,66.59) 93.8,66.89 R90.2 R80.1
  BOTTOM w0.279: R80.1 93.5,67.34 v1(93.5,66.59)
N16853763: length 1.8
  BOTTOM w0.203: U502.2 15.64,60.66 R519.2
N16853765: length 1.6
  BOTTOM w0.203: R520.2 16.04,60.46 U502.3
N16854069: length 1.8
  BOTTOM w0.203: R540.2 21.28,54.87 21.49,55.08 U504.2
N16854076: length 3.4
  BOTTOM w0.203: R536.2 19.19,55.46 20.44,55.46 20.9,55.92 U504.3
N16854778: length 70.2
  L3_INT_1 w0.191: v1(34.43,53.71) 34.43,52.99 30.77,49.34 v1(28.87,49.34)
  L3_INT_1 w0.203: v1(35.42,58.51) 34.43,57.52 v1(34.43,53.71)
  L6_INT_2 w0.191: v1(24.24,55.48) 25.36,54.37 25.36,50.82 24.52,49.98 24.28,49.98 24.09,49.79 24.09,49.18 24.28,48.99 27.97,48.99 28.32,49.34 v1(28.87,49.34)
  L6_INT_2 w0.203: v1(14.75,56.72) 15.09,57.07 21.16,57.07 23.09,55.14 23.9,55.14 v1(24.24,55.48) 24.83,56.07 24.83,56.7 25.73,57.61 26.19,57.61 26.71,58.13 26.71,58.66 27.27,59.22 27.75,59.22 v1(30.19,61.66)
  BOTTOM w0.203: U501.8 29.19,60.88 29.62,61.31 29.85,61.31 v1(30.19,61.66) ; U506.8 34.09,53.37 v1(34.43,53.71) ; v1(28.87,49.34) 28.53,49.68 28.53,49.74 28.15,50.11 U507.8 ; U504.8 23.33,55.52 23.42,55.43 23.44,55.43 23.51,55.36 23.99,55.36 24.12,55.48 v1(24.24,55.48) 24.73,55.48 24.88,55.64 24.88,56.65 24.68,56.86 23.86,56.86 23.46,57.26 C515.1 ; v1(14.75,56.72) 15.09,57.07 15.21,57.07 15.64,57.5 U502.8 ; TP500.1 23.44,63.32 U500.8 ; U503.8 34.85,58.42 34.94,58.51 v1(35.42,58.51)
  BOTTOM w0.406: R523.1 34.79,60.06 35.42,59.42 v1(35.42,58.51) ; C515.1 C514.1 C513.1 C512.1 23.46,62.06 TP500.1 22.61,62.91 R517.1 R632.1
N16855430: length 15.8
  TOP w0.635: L3.2 TPAD505.1 ; L3.2 49.62,58.51 49.62,58.5 C24.1 C26.1 C30.1 R633.1 ; L3.2 49.62,63.51 48.73,64.4 R97.1 R93.1
N16855432: length 16
  TOP w0.635: C8.1 47.45,72.13 48.45,71.13 v1(48.45,68.64) 49.09,68 U1.1
  BOTTOM w0.635: D500.C 46.43,72.29 C501.1 47.99,71.71 48.45,71.26 v1(48.45,68.64)
N16855436: length 14.3
  TOP w0.406: U1.2 TPAD20.1 v1(51.14,65.14)
  TOP w0.762: D5.C 43.02,61.05 L3.1 45.81,63.74 46.16,64.09 46.9,64.09 v1(46.93,64.12)
  L6_INT_2 w0.635: v1(51.14,65.14) 47.94,65.14 v1(46.93,64.12)
N16855465: length 7.4
  TOP w0.406: 52.41,68 TPAD23.1 51.91,64.35 50.25,64.35 R97.2 R93.2
N16855504: length 27.1
  TOP w0.635: J18.2 30.8,70.8 TPAD8.1 29.43,72.93 TS2.1
  L6_INT_2 w0.635: v1(46.32,68.36) 39.94,68.36 39.55,67.97 33.63,67.97 J18.2
  BOTTOM w0.635: v1(46.32,68.36) 45.84,67.89 D500.A
N16868078: length 2.3
  BOTTOM w0.203: U506.2 34.09,50.92 34.25,50.76 35.05,50.76 35.18,50.63 R554.2
N16868081: length 1.5
  BOTTOM w0.203: U506.3 33.69,50.59 33.72,50.57 R555.2
N16868084: length 1.2
  BOTTOM w0.203: U507.2 27.36,47.84 R563.2
N16868087: length 1.3
  BOTTOM w0.203: R564.2 26.96,48.12 U507.3
N16876903: length 2.8
  TOP w0.406: TP44.1 91.15,38.31 R247.2 90.44,38.31 90.31,38.19 Q2.3
N16876912: length 3.1
  TOP w0.406: Q3.3 90.23,35.9 90.49,36.15 R256.2 91.15,36.15 TP49.1
N16877035: length 3.5
  TOP w0.406: R222.1 TPAD38.1 88.43,42.07 88.44,42.05 Q1.1 87.4,41.48 R228.1
N16877205: length 3.3
  TOP w0.406: TPAD41.1 R245.1 R248.1 87.32,38.69 Q2.1
N16877232: length 3.6
  TOP w0.406: TPAD43.1 86.25,36.97 R255.1 R257.1 87.35,36.4 Q3.1
N16979800: length 3.9
  TOP w0.406: R161.1 R186.1
N16990851: length 8
  TOP w0.229: DS1.C 5.24,79.83 v1(4.91,80.15) 4.25,80.15 3.9,79.79 3.9,77.61 4.24,77.26 R4.2
  BOTTOM w0.229: v1(4.91,80.15) R500.1
N16990853: length 3.5
  TOP w0.229: v1(10.29,79.86) 9.26,79.86 DS2.C
  BOTTOM w0.229: Q500.3 v1(10.29,79.86)
N16992788: length 3.4
  TOP w0.406: DS3.C 15.03,76.99 15.02,76.98 15.02,76.9 14.49,76.36 v1(13.8,76.36)
  BOTTOM w0.406: Q501.3 13.54,76.63 v1(13.8,76.36)
N16994780: length 1.5
  TOP w0.406: R13.2 DS1.A
N16994781: length 1.4
  TOP w0.406: R9.2 DS2.A
N16994782: length 2.6
  TOP w0.406: R12.2 12.38,76.45 12.4,76.44 12.81,76.44 13.03,76.66 DS3.A
N17033217: length 6.7
  TOP w0.279: R1.1 106.32,79.72 109.48,76.56 J16.60
N17033342: length 5.8
  TOP w0.279: J16.50 105.95,74.06 R38.1
N17036679: length 8.2
  TOP w0.279: R123.1 106.67,60.03 109.18,62.55 J16.4
  TOP w0.508: R137.1 R123.1
N17037130: length 6.3
  TOP w0.279: J16.10 109.04,64.05 107.18,62.19 R111.1
N17037131: length 6.5
  TOP w0.279: R115.1 106.87,61.17 109.24,63.55 J16.8
N17037133: length 5.7
  TOP w0.279: R62.1 105.84,72.05 J16.42
N17037134: length 5.5
  TOP w0.279: R58.1 109.43,72.6 109.48,72.55 J16.44
N17037135: length 5.9
  TOP w0.279: R81.1 107.53,67.52 108.56,68.55 J16.28
N17037137: length 5.9
  TOP w0.279: R74.1 107.05,69.56 108.05,70.55 J16.36
N17037138: length 5.7
  TOP w0.279: J16.38 107.84,71.05 107.36,70.57 R63.1
N17037139: length 6.1
  TOP w0.279: R102.1 107.32,64.22 108.64,65.55 J16.16
N17037140: length 5.9
  TOP w0.279: R79.1 106.82,68.54 107.83,69.55 J16.32
N17037141: length 6.3
  TOP w0.279: R109.1 106.95,63.21 108.79,65.05 J16.14
N17037142: length 5.9
  TOP w0.279: R91.1 107.73,66.51 108.78,67.55 J16.24
N17037216: length 5.5
  TOP w0.279: J16.48 106.02,73.55 105.96,73.62 R46.1
N17037599: length 8.5
  BOTTOM w0.406: R501.1 103.43,77.12 C500.1 104.86,75.59 104.69,75.41 Y500.1 Y500.4
N17039052: length 6.4
  TOP w0.279: J16.56 108.72,75.56 106.59,77.68 R5.1
N17047156: length 6
  TOP w0.279: R41.2 R35.2 119.43,76.03 v1(118.71,76.03) 118.06,76.03 118.04,76.06 J16.57
  BOTTOM w0.406: v1(118.71,76.03) C547.1
N17049594: length 5
  BOTTOM w0.406: R513.2 101.71,66.76 100.47,68.01 100.47,68.27 100.47,68.27 Y500.3
N17049891: length 6.5
  TOP w0.279: J16.59 118.09,76.56 C548.1 119.09,76.79 R6.2 R3.2 120.1,78.23 TPAD1.1
N17061413: length 6
  TOP w0.279: J16.52 106.47,74.56 R8.1
N17061419: length 6.2
  TOP w0.279: R7.1 106.98,75.06 J16.54
N17062294: length 3.7
  TOP w0.279: R61.2 118.33,72.86 118.33,73.28 118.05,73.55 J16.47
N17062316: length 4.7
  TOP w0.279: R55.2 118.93,73.27 118.93,74.66 118.03,75.56 J16.55
N17063944: length 3.2
  TOP w0.279: J16.5 119.37,63.05 TPAD25.1
N17070752: length 6.9
  TOP w0.203: TPAD22.1 121.98,65.62 121.98,65.72 121.32,66.38 118.94,66.38 118.1,65.55 J16.15
N17070755: length 6.4
  TOP w0.203: TPAD19.1 122.08,66.74 118.68,66.74 117.99,66.05 J16.17
N17070986: length 5.8
  TOP w0.203: 101.43,43.52 100.42,43.52 ; 100.42,43.52 100.42,44.07 100.53,44.17 U12.2 ; 100.42,43.52 98.59,43.52 98.39,43.72 R207.2
N17073684: length 6.7
  TOP w0.203: R184.2 R188.2 ; R184.2 101.43,52.36 101.18,52.61 U3.3 ; R184.2 R183.2 ; R190.2 99.28,51.39 99.78,51.9 R183.2 ; R183.2 100.42,52.54 100.78,52.9 U3.2
N17074032: length 4
  TOP w0.203: U12.3 100.93,44.66 101.28,44.31 101.66,44.31 102.45,43.52 R217.2
N17074703: length 29.1
  TOP w0.203: U10.5 93.69,48.02 ; U12.5 v1(102.68,45.93) ; U3.5 R156.2
  TOP w0.406: R156.2 v1(103.34,54.85) ; 93.69,48.02 94.32,48.02 94.65,47.69 v1(94.65,47.64)
  L3_INT_1 w0.191: v1(94.65,47.64) 96.35,45.93 v1(102.68,45.93) 102.34,46.27 101.72,46.89 101.72,49.22 103.34,50.84 v1(103.34,54.85)
  BOTTOM w0.191: C523.1 101.76,52.89 101.23,52.36 U505.5
  BOTTOM w0.406: v1(103.34,54.85) 102.43,53.93 C523.1
N17076548: length 3
  TOP w0.203: R178.2 R187.2 92.27,50.52 U10.2
N17076571: length 2.5
  TOP w0.203: U10.3 R192.2 R200.2
N17077988: length 2.7
  TOP w0.279: R75.2 118.76,69.56 118.75,69.55 J16.31
N17078013: length 3
  TOP w0.279: R94.2 118.64,65.05 J16.13
N17078038: length 3
  TOP w0.279: J16.9 118.66,64.05 R98.2
N17078063: length 2.8
  TOP w0.279: R108.2 119.18,63.55 J16.7
N17085305: length 9.9
  TOP w0.229: v1(12.04,11.11) 11.76,11.39 11.57,11.39 10.6,12.35 10.6,12.45 v1(10.32,12.74)
  BOTTOM w0.229: v1(10.32,12.74) 10.6,13.02 10.6,15.85 11.04,16.29 11.67,16.29 R617.1 ; v1(12.04,11.11) 11.77,11.37 11.45,11.37 11.15,11.07 U515.3
N17085321: length 8.2
  TOP w0.229: v1(11.24,12.74) 11.24,12.24 11.45,12.03 v1(12.04,12.03)
  BOTTOM w0.229: v1(12.04,12.03) 11.77,11.76 11.45,11.76 11.15,12.07 U515.1 ; v1(11.24,12.74) 10.96,13.02 10.96,15.71 11.19,15.94 11.72,15.94 R618.1
N17090620: length 1.5
  BOTTOM w0.229: R611.2 36.43,18.95 U509.6
N17093251: length 1.3
  BOTTOM w0.203: U509.3 R613.2
N17094456: length 3.7
  TOP w0.406: v1(37.91,18.55) R614.2 R289.1
  BOTTOM w0.229: U509.7 R614.2
  BOTTOM w0.406: R614.2 v1(37.91,18.55)
N17104821: length 45
  TOP w0.279: v1(42.63,39.08) 42.33,39.08 42.09,39.32 U14.8 ; U11.8 41.28,49.48 v1(41.57,49.77) ; U13.8 v1(43.32,43.22) ; U22.8 62.18,37.24 61.94,37.01 v1(60.24,37.01) 60.24,37.37 TPAD42.1 ; R234.1 51.27,39.43 51.6,39.1 v1(52.11,39.1) 51.74,38.73 51.74,38.44 51.43,38.13 U16.8
  TOP w0.406: C66.1 51.02,40.09 R234.1
  L3_INT_1 w0.191: 58.46,38.31 59.76,37.01 v1(60.24,37.01) ; v1(52.11,39.1) 52.45,38.76 52.45,38.71 52.84,38.31 ; v1(42.63,39.08) 42.63,42.53 v1(43.32,43.22)
  L3_INT_1 w0.203: 58.46,38.31 52.84,38.31
  L6_INT_2 w0.191: v1(41.57,49.77) 42.04,49.77 42.89,48.92 42.89,47.15 43.32,46.72 v1(43.32,43.22) ; v1(42.63,39.08) 43.47,39.91 47,39.91 47.15,39.76 49.46,39.76 50.12,39.1 v1(52.11,39.1)
  BOTTOM w0.279: R552.2 41.41,50.12 41.57,49.97 v1(41.57,49.77)
  BOTTOM w0.406: R553.1 41.52,50.71 R552.2
N17105995: length 2.6
  TOP w0.279: 27.83,52.1 U9.7
  TOP w0.406: R177.2 27.97,52.1 27.83,52.1
N17106020: length 2.8
  TOP w0.279: U9.8 27.71,52.75 27.83,52.87
  TOP w0.406: R154.2 28.59,53.73 28.59,53.69 28.16,53.26 28.16,53.2 27.83,52.87
N17106045: length 3
  TOP w0.279: U9.9 27.47,53.4 27.83,53.76
  TOP w0.406: R150.2 28,54.16 28,53.93 27.83,53.76
N17106070: length 3.3
  TOP w0.279: 27.83,54.93 27.83,54.7 27.18,54.05 U9.10
  TOP w0.406: R149.2 28.56,55.61 28.51,55.61 27.83,54.93
N17106135: length 1.9
  TOP w0.279: 21.68,59.07 21.68,58.75 21.64,58.71 U9.17
  TOP w0.406: R128.2 21.68,59.07
N17106160: length 2.1
  TOP w0.279: 22.36,59.07 22.29,58.99 U9.16
  TOP w0.406: R129.2 22.36,59.07
N17106205: length 2.2
  TOP w0.279: U9.19 20.34,58.7 20.27,58.77 20.27,58.81 20.02,59.07
  TOP w0.406: 20.02,59.07 19.93,59.15 19.89,59.15 R126.2
N17106230: length 2.1
  TOP w0.279: 20.99,59.07 U9.18
  TOP w0.406: R127.2 20.99,59.07 20.99,59.07
N17109048: length 6.6
  TOP w0.279: R2.1 106.54,78.7 109.18,76.06 J16.58
N17110598: length 5.6
  TOP w0.406: J21.2 8.6,24.92 10.49,26.81 D9.A
N17110600: length 8.7
  TOP w0.406: R276.2 R279.2 10.83,29.42 10.45,29.04 TP54.1 8.32,29.04 7.82,28.54 D9.C
N17111325: length 2.2
  TOP w0.279: U9.15 22.94,58.62 23.38,59.07
  TOP w0.406: R130.2 23.38,59.07
N17111345: length 2.5
  TOP w0.279: U9.14 23.59,58.49 23.84,58.75 24.08,58.75 24.4,59.07
  TOP w0.406: R131.2 24.4,59.07
N17121372: length 2.5
  TOP w0.406: J10.20 R148.1
N17121375: length 2.5
  TOP w0.406: J10.18 R141.1
N17121420: length 3.2
  TOP w0.406: J10.12 R114.1
N17121423: length 2.5
  TOP w0.406: J10.14 R122.1
N17121426: length 2.5
  TOP w0.406: J10.16 R136.1
N17122140: length 2.3
  TOP w0.406: J10.11 R113.2
N17122143: length 2.3
  TOP w0.406: J10.13 R121.2
N17142860: length 1.9
  BOTTOM w0.229: R511.2 24.19,65.85 24.45,65.59 U500.2
N17142862: length 2
  BOTTOM w0.229: R512.2 24.85,65.8 U500.3
N17147847: length 12.9
  TOP w0.406: v1(35.95,32.98) 35.95,33.23 TP50.1 35.18,33.32 R267.2 R266.2 31.61,33.32 31.42,33.13 30.96,33.13 30,34.1 TS13.1
  L3_INT_1 w0.191: v1(35.95,32.98) 35.95,32.14 J3.7
N17164200: length 2.9
  TOP w0.406: J1.1 R34.2 R40.2
N17164202: length 2.9
  TOP w0.406: R39.2 R14.2 J1.4
N17172615: length 3
  BOTTOM w0.406: TPAD501.1 R504.1 R502.1 8.34,78.55 Q500.1
N17172906: length 4.9
  BOTTOM w0.406: Q501.1 14.32,77.83 13.91,78.24 TPAD500.1 R503.1 R505.1
N17258367: length 3
  TOP w0.406: J10.7 TPAD24.1
N17258370: length 3
  TOP w0.406: 87.46,62.57 TPAD26.1
N17322992: length 6
  TOP w0.203: TPAD18.1 121.93,67.45 121.83,67.55 J16.23
N17322995: length 6
  TOP w0.203: J16.27 121.87,68.55 121.93,68.62 TPAD16.1
N17323030: length 3.4
  TOP w0.203: J16.41 117.99,72.05 118.17,71.87 118.17,71.51 TPAD11.1
N17323033: length 6.2
  TOP w0.203: J16.43 117.99,72.55 118.8,71.75 118.8,71.62 119.2,71.21 TPAD10.1
N17330326: length 3.9
  TOP w0.635: J4.3 R283.2 R282.2 R287.2
N17344806: length 1.2
  BOTTOM w0.203: R528.2 29.19,58.11 U501.2
N17344809: length 2.2
  BOTTOM w0.203: R534.2 28.94,57.38 28.79,57.53 U501.3
N17345453: length 1.2
  BOTTOM w0.203: R537.2 34.46,56.46 34.4,56.52 U503.2
N17347641: length 37.8
  L3_INT_1 w0.191: v1(16.01,47.46) 16.01,47.94 13.98,49.98 13.93,49.98 13.25,50.66 13.25,55.9 14.89,57.54 v1(14.95,57.54)
  L6_INT_2 w0.191: v1(14.95,57.54) 15.53,57.54 17.34,59.34 24.64,59.34 25.94,60.65 25.97,60.65 26.24,60.93 26.24,60.96 26.25,60.96 26.25,61.26 26.34,61.36 26.34,61.37 26.62,61.65 26.64,61.65 27.74,62.75 31.71,62.75 v1(33.15,61.3) 33.15,59.65 33.01,59.51 v1(33.01,58.42)
  BOTTOM w0.203: v1(33.01,58.42) U503.6
  BOTTOM w0.406: v1(33.15,61.3) 33.26,61.19 R523.2
N17349405: length 3.3
  TOP w0.279: v1(27.7,55.74) 27.31,55.35 U9.12
  BOTTOM w0.406: R532.2 R531.2 27.32,56.12 v1(27.7,55.74)
N17381520: length 3.8
  BOTTOM w0.191: U505.2 99.38,53.52 99.32,53.59 98.17,53.59 98.11,53.53 R545.2 R549.2
N17382056: length 2.5
  BOTTOM w0.203: 99.78,54.09 U505.3
  BOTTOM w0.406: 99.78,54.09 100.44,54.75 R539.2
N17382061: length 3
  BOTTOM w0.191: U505.6 100.18,51.07 100.32,50.94 101.38,50.94 101.66,51.22 R551.2
N17414813: length 3.7
  TOP w0.279: U9.29 13.94,52.75 13.68,52.49 13.68,51.83 13.25,51.39
  TOP w0.406: 13.25,51.39 12.61,50.76 R189.2 12.52,50.76
N17414865: length 6.4
  TOP w0.279: R215.2 R216.2
  TOP w0.33: R215.2 26.35,46.28 26.56,46.48 26.56,47.1 26.33,47.33 25.31,47.33 25.18,47.46 25.18,47.94 25.44,48.2 U9.1
N17423098: length 1.4
  TOP w0.33: D7.A R262.2
N17437399: length 58.6
  TOP w0.406: SW6.4 15.75,8.49 16.1,8.14 16.1,5.85 15.75,5.5 SW6.2 14.92,4.42 14.59,4.75 14.59,5.2 v1(14.43,5.36) 14.27,5.52 C116.1 13.4,5.55 R334.2 ; R203.1 v1(11.93,48.68)
  L3_INT_1 w0.191: v1(11.93,48.68) 11.93,45.25 9.75,43.07 9.75,23.23 9.49,22.97 9.49,13.36 9.79,13.06 9.79,7.97 12.39,5.36 v1(14.43,5.36)
N17489769: length 2.7
  TOP w0.279: v1(33.39,55.81) 33.39,54.7 R153.2
  BOTTOM w0.203: v1(33.39,55.81) 33.39,55.93 34,56.54 U503.3
N20564874: length 2.8
  TOP w0.279: U22.5 65.75,36.02 v1(66.52,36.79) R252.2
N20580503: length 3.4
  TOP w0.279: R214.2 40.55,46.24 39.39,46.24 39.07,46.56 U11.5
N20620060: length 2.3
  TOP w0.406: P1.17 R322.2
N20620064: length 2.3
  TOP w0.406: P1.27 R317.2
N20620068: length 2.2
  TOP w0.406: P1.45 R332.2
N20620072: length 2.2
  TOP w0.406: P1.47 R331.2
N20620358: length 2.3
  TOP w0.406: P1.31 R315.2
N20620361: length 2.3
  TOP w0.406: P1.29 R316.2
N20620364: length 2.3
  TOP w0.406: P1.25 R318.2
N20620367: length 2.3
  TOP w0.406: P1.23 R319.2
N20620674: length 2.3
  TOP w0.406: P1.21 R320.2
N20620694: length 2.3
  TOP w0.406: P1.19 R321.2
N20620726: length 2.3
  TOP w0.406: P1.33 R314.2
N20620746: length 2.3
  TOP w0.406: P1.35 R313.2
N20620840: length 2.3
  TOP w0.406: P1.37 R312.2
N20620843: length 2.3
  TOP w0.406: P1.39 R311.2
N20620846: length 2.3
  TOP w0.406: P1.41 R310.2
N20620849: length 2.6
  TOP w0.406: P1.43 30.19,9.61 R309.2
N20712518: length 5.5
  TOP w0.406: R333.2 105.37,8.09 106.64,6.82 SW2.1
N20712658: length 6.8
  TOP w0.406: 109.06,24.98 106.82,24.98 106.13,25.66 R280.2
N20743373: length 2
  TOP w0.279: v1(60.72,36.32) 60.67,36.32 60.67,36.28 60.71,36.28 60.97,36.02 U22.10
  BOTTOM w0.406: v1(60.72,36.32) 60.71,36.32 60.77,36.38 R589.2
N20743518: length 2.4
  TOP w0.279: U11.10 39.07,51.01 39.62,51.55 39.62,52 R176.2

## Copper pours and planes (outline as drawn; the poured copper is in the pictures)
P3V3_ENETSW on L5_PWR_2: 95.44,51.65 95.44,47.84 96.91,46.37 104.36,46.37 106.34,48.35 106.34,57.74 103.57,60.51 100.83,60.51 99.68,59.37 99.68,56.3 98.87,55.48 98.87,54.49 98.95,54.42 98.95,53.22 97.78,52.06 95.85,52.06
P3V3_SDA on L4_PWR_1: 11.44,24.9 11.44,8.88 12.51,7.81 18.35,7.81 24.37,13.83 33.74,13.83 36.72,16.8 36.72,21.52 35.6,22.64 24.88,22.64 23.89,23.63 23.89,27.49 22.03,29.35 15.89,29.35
P3V3_SW on L5_PWR_2: 3.09,25.89 3.09,22.11 5.17,20.03 10.33,20.03 11.62,21.32 33.69,21.32 37.43,25.05 37.43,32.14 39.84,34.55 45.07,34.55 47.26,36.74 47.26,38.82 49.14,40.7 49.14,45.83 52.29,48.98 53.17,48.98 53.17,51.62 49.67,55.13 43.07,55.13 36.16,48.22 36.16,41.01 22.03,26.88 4.08,26.88
P5V_SDA on L5_PWR_2: 7.18,19.01 7.18,9.08 26.91,9.08 26.91,19.01
VBAT on TOP: 5.73,66.08 5.73,62.49 5.96,62.27 7.84,62.27 8.85,63.28 13.42,63.28 14.44,62.27 18.88,62.27 19.6,62.98 19.6,66.46 19.47,66.58 16.04,66.58 15.28,67.35 14.08,67.35 13.07,66.33 5.98,66.33
VBAT on L4_PWR_1: 34.68,73.24 34.68,64.17 46.8,52.06 46.8,21.75 46.62,21.58 1.71,21.58 -4.33,27.62 -4.33,69.2 -0.29,73.24
VDD_MCU on L5_PWR_2: 55.21,74.25 55.21,67.02 51.68,63.49 51.68,43.06 58.05,36.69 77.89,36.69 82.99,41.79 82.99,69.61 65.11,69.61 60.46,74.25 ; 1 cut-out
VDD_MCU_ENETSW on L4_PWR_1: 89.07,57.39 89.07,42.83 92.67,39.23 106.34,39.23 106.64,39.53 106.64,47.48 108.75,49.59 108.75,57.67 108.04,58.38 90.06,58.38
VDD_MCU_PERH on L4_PWR_1: 80.33,13.37 69.76,23.94 52.51,23.94 50.53,25.92 50.53,34.88 48.81,36.61 48.81,41.08 49.11,41.39 55.89,41.39 55.89,60.95 58.92,63.97 84.44,63.97 86.91,61.5 86.91,39.76 89.6,37.07 89.6,31.71 99.89,21.42 99.89,12.23 96.08,8.42 87.49,8.42 82.54,13.37
VDD_MCU_PERH on L5_PWR_2: 82.54,69.48 83.12,68.9 83.12,55.51 87.52,51.12 94.93,51.12 96.63,52.82 115.84,52.82 115.84,59.45 99.61,75.68 91.3,75.68 90.56,76.41 21.91,76.41 20.46,74.97 20.46,72.55 21.17,71.84 28.84,71.84 30.06,73.06 32.02,73.06 34.46,70.62 35.5,70.62 37.63,72.76 44.62,72.76 45.35,72.02 50.61,72.02 53.02,74.43 71.29,74.43 71.56,74.15 60.74,74.15 60.31,73.72 60.31,73.44 64.27,69.48
PVEXT_SBC on L6_INT_2: 19.55,57.01 19.55,54.95 19.75,54.75 21.91,54.75 23.94,52.72 23.94,51.45 23.15,50.66 23.15,47.46 24.93,45.68 30.8,45.68 31.81,46.7 31.81,51.78 31.31,52.28 30.92,52.28 30.39,51.75 27.09,51.75 25.49,50.15 25.13,50.15 24.93,50.35 24.93,50.56 25.41,51.04 25.41,54.14 24.04,55.51 22.64,55.51 21.09,57.06 19.6,57.06
SDA_USBSHIELD on TOP (solid shape): 2.47,17.41 5.14,17.41 5.14,15.39 3.89,15.39 3.89,16.39 0.56,16.39 0.56,18.12 2.47,18.12
SDA_USBSHIELD on TOP (solid shape): 5.14,8.93 2.47,8.93 2.47,8.21 0.56,8.21 0.56,9.94 3.89,9.94 3.89,10.94 5.14,10.94
VSUP on TOP: 20.28,63.03 20.89,62.42 24.35,62.42 25.36,61.4 31.75,61.4 32.14,60.74 34,60.74 35.67,62.42 35.67,64.65 35.14,65.19 33.79,65.19 32.42,63.82 30.47,63.82 27.52,66.76 24.73,66.76 23.41,68.08 23.41,70.85 23.08,71.18 20.56,71.18 20.28,70.9
N16745986 on TOP: 35.98,64.96 35.98,62.82 34.79,61.63 31.74,61.63 31.51,61.4 31.51,60.39 32.7,59.19 32.7,58.3 32.32,57.92 30.37,57.92 30.29,57.85 30.29,57.41 30.44,57.26 34.07,57.26 34.56,57.74 35.85,57.74 37.1,58.99 37.1,61 38.87,62.77 38.87,64.53 38.09,65.31 36.33,65.31
N16745986 on L5_PWR_2: 12.56,56.22 12.56,50.23 20.1,42.68 22.57,42.68 22.97,43.09 22.97,47.03 21.7,48.3 21.7,49.16 25.9,53.35 29.27,53.35 29.53,53.6 31.94,53.6 34.12,55.79 34.12,61.76 33.67,62.22 29.91,62.22 28.92,61.22 28.92,58.33 26.63,56.04 25.16,56.04 24.42,56.78 22.39,56.78 19.52,53.91 16.57,53.91 13.96,56.53 12.87,56.53

Small or netless copper shapes (teardrops, artwork), in the pictures only: 1 on TOP, 1 on BOTTOM, 1 on L2_GND_1, 1 on L3_INT_1, 1 on L4_PWR_1, 1 on L5_PWR_2, 1 on L6_INT_2

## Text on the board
BOTTOM: 170-29643 REV C | 8 OF 14 | SECONDARY SIDE
Board Geometry/Soldermask Bottom: 12 OF 14 | SECONDARY SOLDERMASK
Ref Des/Silkscreen Bottom: ** | * | NC | GND | LIN | CANL | CANH | VBAT | P3V3 | 14 OF 14 | SECONDARY SILKSCREEN
User.Comments: 1 OF 1 | TEST PROBE | 1/1 | 1
TOP: 1 OF 14 | PRIMARY SIDE
Board Geometry/Soldermask Top: 9 OF 14 | PRIMARY SOLDERMASK
